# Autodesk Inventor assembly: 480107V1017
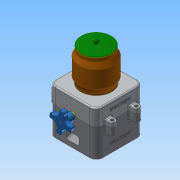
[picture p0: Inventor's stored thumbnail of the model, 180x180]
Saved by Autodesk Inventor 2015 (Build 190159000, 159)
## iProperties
Created: 2018-01
Part Number: 480107V1017
Document SubType Name: Assembly
Designer: user
Author: user
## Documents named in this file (9)
- C:\Users\user\Desktop\480107V1017\480107V1017.iam
- C:\Users\user\Desktop\480107V1017\본체.ipt
- C:\Users\user\Desktop\480107V1017\핸들축.ipt
- C:\Users\user\Desktop\480107V1017\본체커버.ipt
- C:\Users\user\Desktop\480107V1017\용기.ipt
- C:\Users\user\Desktop\480107V1017\용기캡.ipt
- C:\Users\user\Desktop\480107V1017\핸들.ipt
- C:\Users\user\Desktop\480107V1017\볼트 M3x12.ipt
- C:\Users\user\Desktop\480107V1017\볼트 M4x12.ipt
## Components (2 placed, 2 different names)
1. 핸들축:1
2. 핸들:1
